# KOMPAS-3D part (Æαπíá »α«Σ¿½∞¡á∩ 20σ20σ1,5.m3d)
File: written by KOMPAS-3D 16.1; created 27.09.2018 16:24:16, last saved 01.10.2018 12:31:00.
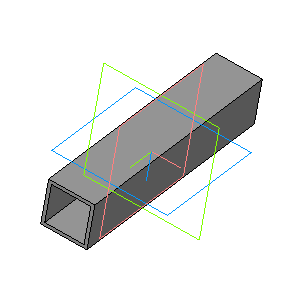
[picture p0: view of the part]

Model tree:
1. Эскиз:1
2. Операция выдавливания:1  (labels: Труба профильная 25х25х1,5)
     Расстояние 2 = 10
